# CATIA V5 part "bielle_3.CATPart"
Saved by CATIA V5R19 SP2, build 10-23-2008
Part number: bielle_3
Bounding box of the stored display mesh (mm): x 0 to 10, y -70 to 10, z -10 to 10
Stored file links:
  C:\Users\Guillaume\Desktop\ETUDES\IFMA\S3\IAO\Projet IAO\ggaubert_1504\bielle_3.CATPart
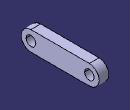
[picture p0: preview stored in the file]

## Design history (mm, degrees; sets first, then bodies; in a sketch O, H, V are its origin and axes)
Parameters
  entraxe_bielle_3 = 60 mm
Body1 (main body)
  Sketch1 on yz-plane, origin (0, 0, 0), H (0, 1, 0), V (0, 0, 1)
    line L1 (-60, 10) -> (0, 10)
    arc A1 centre (0, 0) radius 10 from (0, 10) to (0, -10) cw
    point P3 (0, 0)
    line L2 (0, -10) -> (-60, -10)
    arc A2 centre (-60, 0) radius 10 from (-60, -10) to (-60, 10) cw
    point P6 (-60, 0)
    distance L1 L2 = 20
    distance P3 P6 = 60 {= entraxe_bielle_3}
    horizontal: L1 H
    tangency: A1 L1, L2 A1, A2 L1, A2 L2
    coincidence: P3 O
  Sketch2 on yz-plane, origin (0, 0, 0), H (0, 1, 0), V (0, 0, 1)
    circle A1 centre (0, 0) radius 5
    circle A2 centre (-60, 0) radius 5
    point P1 (-60, 0)
    radius A1 = 5
    radius A2 = 5
    distance P1 O = 60 {= entraxe_bielle_3}
    coincidence: P1 H
  Pad1: profile Sketch1, direction (1, 0, 0), length 10
  Pocket1: profile Sketch2, direction (-1, 0, 0), up to end face of Pad1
